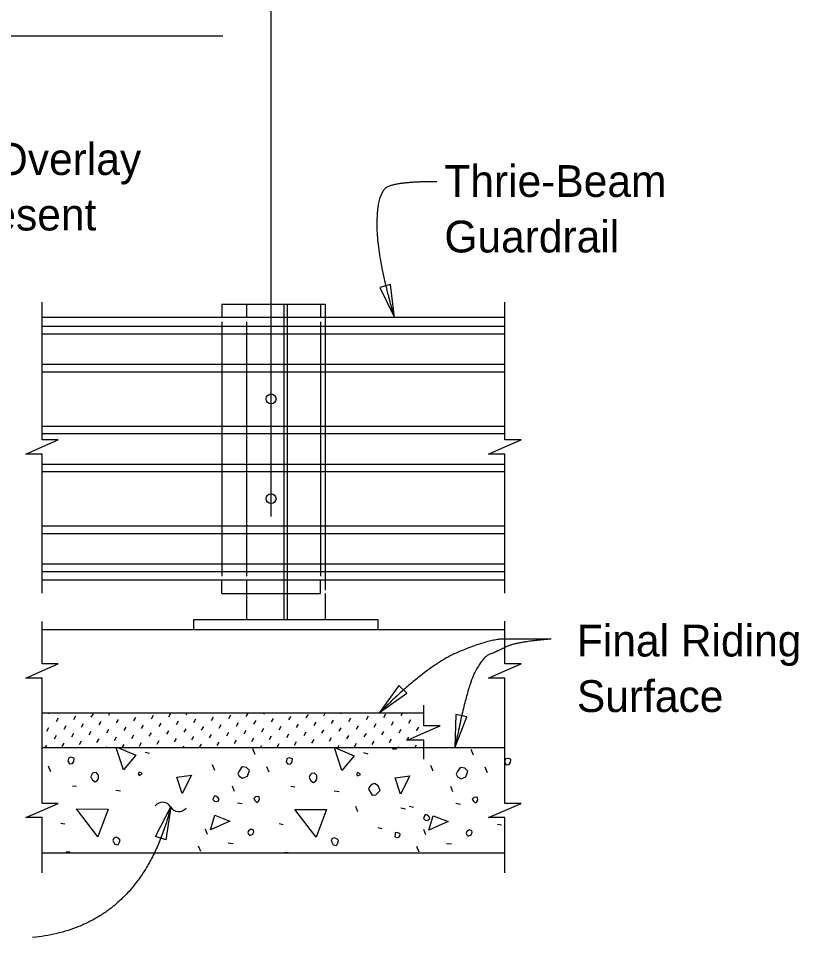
# Model space of a CAD drawing. Extents: x 21516.9 to 21586.2, y 56154.4 to 56193.6.
# Drawn here: x 21533.29 to 21538.24, y 56170.02 to 56175.85 of the extents above; entities that cross this region are included whole.
import ezdxf

# ---------------------------------------------------------------- set-up
doc = ezdxf.new("R2010")
doc.units = 0
for name, color, linetype in [('AdhocPoint_dp', 7, 'Continuous'), ('Border', 7, 'Continuous'), ('Patterning', 7, 'Continuous'), ('PlotBorder_dp', 7, 'Continuous'), ('TextMisc', 7, 'Continuous')]:
    doc.layers.add(name, color=color, linetype=linetype)

msp = doc.modelspace()

# ---------------------------------------------------------------- linework, layer by layer
at = {"layer": 'AdhocPoint_dp'}
for p, q in [((21533.4431, 56171.9698), (21536.3787, 56171.9698)), ((21535.8644, 56171.4388), (21533.4431, 56171.4388)), ((21536.3787, 56171.2198), (21533.4431, 56171.2198)), ((21533.4431, 56170.5532), (21536.3787, 56170.5532))]:
    msp.add_line(p, q, dxfattribs=at)
at = {"layer": 'Border'}
for p, q in [((21534.979, 56172.0324), (21534.979, 56174.0324)), ((21534.9998, 56172.0324), (21534.9998, 56174.0324)), ((21535.2394, 56174.0324), (21535.2394, 56172.2194)), ((21534.7394, 56173.9205), (21534.7394, 56172.3086))]:
    msp.add_line(p, q, dxfattribs=at)
at = {"layer": 'Patterning'}
for p, q in [((21534.5832, 56174.0324), (21535.2082, 56174.0324)), ((21534.5832, 56174.0324), (21534.5832, 56173.9491)), ((21535.2082, 56174.0324), (21535.2082, 56173.9491)), ((21534.5832, 56173.9205), (21534.5832, 56172.3086)), ((21535.2082, 56173.9205), (21535.2082, 56172.3086)), ((21534.5832, 56172.1991), (21534.5832, 56172.2824)), ((21535.2082, 56172.1991), (21535.2082, 56172.2824)), ((21534.5832, 56172.1991), (21535.2082, 56172.1991)), ((21533.4856, 56171.436), (21533.4872, 56171.4388)), ((21533.8663, 56171.4261), (21533.8737, 56171.4388)), ((21534.3577, 56171.4291), (21534.3633, 56171.4388)), ((21534.7384, 56171.4192), (21534.7498, 56171.4388)), ((21534.8491, 56171.4321), (21534.8529, 56171.4388)), ((21535.2298, 56171.4222), (21535.2394, 56171.4388)), ((21535.3404, 56171.4352), (21535.3425, 56171.4388)), ((21535.7212, 56171.4252), (21535.729, 56171.4388)), ((21535.8318, 56171.4382), (21535.8321, 56171.4388)), ((21533.5344, 56171.3872), (21533.5474, 56171.4096)), ((21533.6451, 56171.4002), (21533.658, 56171.4226)), ((21533.7557, 56171.4131), (21533.7687, 56171.4355)), ((21533.8045, 56171.3643), (21533.8175, 56171.3867)), ((21533.9152, 56171.3773), (21533.9281, 56171.3996)), ((21534.0258, 56171.3902), (21534.0388, 56171.4126)), ((21534.1364, 56171.4032), (21534.1494, 56171.4256)), ((21534.2471, 56171.4161), (21534.26, 56171.4385)), ((21534.2959, 56171.3673), (21534.3089, 56171.3897)), ((21534.4065, 56171.3803), (21534.4195, 56171.4027)), ((21534.5172, 56171.3932), (21534.5301, 56171.4156)), ((21534.6278, 56171.4062), (21534.6408, 56171.4286)), ((21534.7873, 56171.3703), (21534.8002, 56171.3927)), ((21534.8979, 56171.3833), (21534.9109, 56171.4057)), ((21535.0085, 56171.3963), (21535.0215, 56171.4187)), ((21535.1192, 56171.4092), (21535.1321, 56171.4316)), ((21535.168, 56171.3604), (21535.181, 56171.3828)), ((21535.2786, 56171.3734), (21535.2916, 56171.3957)), ((21535.3893, 56171.3863), (21535.4022, 56171.4087)), ((21535.4999, 56171.3993), (21535.5129, 56171.4217)), ((21535.6105, 56171.4122), (21535.6235, 56171.4346)), ((21535.6594, 56171.3634), (21535.6723, 56171.3858)), ((21535.77, 56171.3764), (21535.783, 56171.3988)), ((21533.4726, 56171.3254), (21533.4856, 56171.3478)), ((21533.5833, 56171.3384), (21533.5962, 56171.3608)), ((21533.6939, 56171.3513), (21533.7069, 56171.3737)), ((21533.7427, 56171.3025), (21533.7557, 56171.3249)), ((21533.8534, 56171.3155), (21533.8663, 56171.3378)), ((21533.964, 56171.3284), (21533.977, 56171.3508)), ((21534.0746, 56171.3414), (21534.0876, 56171.3638)), ((21534.1853, 56171.3543), (21534.1982, 56171.3767)), ((21534.2341, 56171.3055), (21534.2471, 56171.3279)), ((21534.3447, 56171.3185), (21534.3577, 56171.3409)), ((21534.4554, 56171.3314), (21534.4683, 56171.3538)), ((21534.566, 56171.3444), (21534.579, 56171.3668)), ((21534.6766, 56171.3574), (21534.6896, 56171.3798)), ((21534.7255, 56171.3085), (21534.7384, 56171.3309)), ((21534.8361, 56171.3215), (21534.8491, 56171.3439)), ((21534.9467, 56171.3345), (21534.9597, 56171.3569)), ((21535.0574, 56171.3474), (21535.0703, 56171.3698)), ((21535.2168, 56171.3116), (21535.2298, 56171.3339)), ((21535.3275, 56171.3245), (21535.3404, 56171.3469)), ((21535.4381, 56171.3375), (21535.4511, 56171.3599)), ((21535.5487, 56171.3504), (21535.5617, 56171.3728)), ((21535.5976, 56171.3016), (21535.6105, 56171.324)), ((21535.7082, 56171.3146), (21535.7212, 56171.337)), ((21535.8188, 56171.3275), (21535.8318, 56171.3499)), ((21533.5215, 56171.2766), (21533.5344, 56171.299)), ((21533.6321, 56171.2895), (21533.6451, 56171.3119)), ((21533.7916, 56171.2537), (21533.8045, 56171.2761)), ((21533.9022, 56171.2666), (21533.9152, 56171.289)), ((21534.0128, 56171.2796), (21534.0258, 56171.302)), ((21534.1235, 56171.2926), (21534.1364, 56171.3149)), ((21534.1723, 56171.2437), (21534.1853, 56171.2661)), ((21534.2829, 56171.2567), (21534.2959, 56171.2791)), ((21534.3936, 56171.2696), (21534.4065, 56171.292)), ((21534.5042, 56171.2826), (21534.5172, 56171.305)), ((21534.6148, 56171.2956), (21534.6278, 56171.318)), ((21534.6637, 56171.2467), (21534.6766, 56171.2691)), ((21534.7743, 56171.2597), (21534.7873, 56171.2821)), ((21534.8849, 56171.2727), (21534.8979, 56171.2951)), ((21534.9956, 56171.2856), (21535.0085, 56171.308)), ((21535.1062, 56171.2986), (21535.1192, 56171.321)), ((21535.155, 56171.2498), (21535.168, 56171.2721)), ((21535.2657, 56171.2627), (21535.2786, 56171.2851)), ((21535.3763, 56171.2757), (21535.3893, 56171.2981)), ((21535.4869, 56171.2886), (21535.4999, 56171.311)), ((21535.6464, 56171.2528), (21535.6594, 56171.2752)), ((21535.757, 56171.2657), (21535.77, 56171.2881)), ((21533.4626, 56171.2198), (21533.4726, 56171.2372)), ((21533.5703, 56171.2277), (21533.5833, 56171.2501)), ((21533.6809, 56171.2407), (21533.6939, 56171.2631)), ((21533.8491, 56171.2199), (21533.8534, 56171.2272)), ((21533.9522, 56171.2199), (21533.964, 56171.2402)), ((21534.0617, 56171.2308), (21534.0746, 56171.2531)), ((21534.3388, 56171.2199), (21534.3447, 56171.2302)), ((21534.4424, 56171.2208), (21534.4554, 56171.2432)), ((21534.553, 56171.2338), (21534.566, 56171.2562)), ((21534.7253, 56171.22), (21534.7255, 56171.2203)), ((21534.7949, 56171.1768), (21534.7808, 56171.2121)), ((21534.8284, 56171.22), (21534.8361, 56171.2333)), ((21534.9338, 56171.2238), (21534.9467, 56171.2462)), ((21535.0444, 56171.2368), (21535.0574, 56171.2592)), ((21535.2149, 56171.22), (21535.2168, 56171.2233)), ((21535.3181, 56171.2201), (21535.3275, 56171.2363)), ((21535.4251, 56171.2268), (21535.4381, 56171.2492)), ((21535.5358, 56171.2398), (21535.5487, 56171.2622)), ((21535.7046, 56171.2201), (21535.7082, 56171.2263)), ((21535.8077, 56171.2201), (21535.8188, 56171.2393)), ((21536.1796, 56171.1732), (21536.1655, 56171.2086)), ((21534.0967, 56171.1927), (21534.125, 56171.1856)), ((21535.4813, 56171.1891), (21535.5096, 56171.1821)), ((21533.498, 56171.0678), (21533.4839, 56171.1031)), ((21534.5386, 56171.076), (21534.5245, 56171.1114)), ((21534.8827, 56171.0642), (21534.8686, 56171.0996)), ((21535.9233, 56171.0725), (21535.9091, 56171.1078)), ((21536.2674, 56171.0607), (21536.2532, 56171.0961)), ((21533.6359, 56170.9794), (21533.6607, 56170.9759)), ((21534.6641, 56170.9434), (21534.6517, 56170.977)), ((21535.0206, 56170.9759), (21535.0453, 56170.9723)), ((21536.0488, 56170.9399), (21536.0364, 56170.9735)), ((21533.9117, 56170.9511), (21533.9417, 56170.9458)), ((21535.2964, 56170.9476), (21535.3264, 56170.9423)), ((21534.6829, 56170.8716), (21534.713, 56170.8663)), ((21536.0676, 56170.868), (21536.0977, 56170.8627)), ((21535.4448, 56170.8132), (21535.4325, 56170.8468)), ((21535.7189, 56170.8397), (21535.7471, 56170.8327)), ((21535.7713, 56170.8497), (21535.7995, 56170.8427)), ((21533.5617, 56170.7425), (21533.5882, 56170.7372)), ((21534.4926, 56170.6707), (21534.4803, 56170.7042)), ((21534.9463, 56170.739), (21534.9729, 56170.7337)), ((21535.5721, 56170.7142), (21535.5986, 56170.7089)), ((21535.8773, 56170.6671), (21535.865, 56170.7007)), ((21536.331, 56170.7354), (21536.3575, 56170.7301)), ((21534.4502, 56170.5611), (21534.4361, 56170.5964)), ((21534.6228, 56170.617), (21534.6547, 56170.6135)), ((21535.8349, 56170.5575), (21535.8208, 56170.5929)), ((21536.0075, 56170.6135), (21536.0393, 56170.6099))]:
    msp.add_line(p, q, dxfattribs=at)
for points in [[(21533.9594, 56171.0802), (21533.914, 56171.2198)], [(21533.9279, 56171.2198), (21534.0372, 56171.1721), (21533.9594, 56171.0802)], [(21535.3441, 56171.0766), (21535.2975, 56171.2198)], [(21535.3044, 56171.2198), (21535.4219, 56171.1685), (21535.3441, 56171.0766)], [(21535.6662, 56171.2198), (21535.6687, 56171.2139), (21535.6652, 56171.2174)], [(21535.6687, 56171.2139), (21535.6899, 56171.2139), (21535.6959, 56171.2198)], [(21533.6076, 56171.135), (21533.6165, 56171.119), (21533.6359, 56171.1208), (21533.6447, 56171.1332), (21533.6465, 56171.1526), (21533.6341, 56171.1579), (21533.6253, 56171.1597), (21533.6147, 56171.1562), (21533.6112, 56171.1526), (21533.6076, 56171.135)], [(21534.9923, 56171.1314), (21535.0011, 56171.1155), (21535.0206, 56171.1173), (21535.0294, 56171.1297), (21535.0312, 56171.1491), (21535.0188, 56171.1544), (21535.01, 56171.1562), (21534.9994, 56171.1526), (21534.9958, 56171.1491), (21534.9923, 56171.1314)], [(21536.377, 56171.1279), (21536.3858, 56171.112), (21536.4053, 56171.1137), (21536.4141, 56171.1261), (21536.4159, 56171.1456), (21536.4035, 56171.1509), (21536.3947, 56171.1526), (21536.384, 56171.1491), (21536.3805, 56171.1456), (21536.377, 56171.1279)], [(21534.6924, 56171.0389), (21534.7154, 56171.0265), (21534.7454, 56171.0389), (21534.7578, 56171.076), (21534.7401, 56171.0937), (21534.7172, 56171.099), (21534.7065, 56171.0919), (21534.6942, 56171.0725), (21534.6853, 56171.0566), (21534.6924, 56171.0389)], [(21536.0771, 56171.0353), (21536.1001, 56171.023), (21536.1301, 56171.0353), (21536.1425, 56171.0725), (21536.1248, 56171.0901), (21536.1018, 56171.0954), (21536.0912, 56171.0884), (21536.0789, 56171.0689), (21536.07, 56171.053), (21536.0771, 56171.0353)], [(21533.7526, 56171.036), (21533.7632, 56171.0147), (21533.7809, 56171.0041), (21533.795, 56171.0147), (21533.8021, 56171.0254), (21533.8021, 56171.0466), (21533.7862, 56171.0625), (21533.7667, 56171.0607), (21533.7579, 56171.0519), (21533.7526, 56171.036)], [(21534.0584, 56171.0448), (21534.0778, 56171.0536), (21534.0708, 56171.0607), (21534.0584, 56171.066), (21534.0531, 56171.0536), (21534.0584, 56171.0448)], [(21534.3318, 56170.9293), (21534.2982, 56171.0336), (21534.3919, 56171.0459), (21534.3318, 56170.9293)], [(21535.1373, 56171.0324), (21535.1479, 56171.0112), (21535.1655, 56171.0006), (21535.1797, 56171.0112), (21535.1868, 56171.0218), (21535.1868, 56171.043), (21535.1708, 56171.0589), (21535.1514, 56171.0572), (21535.1426, 56171.0483), (21535.1373, 56171.0324)], [(21535.4431, 56171.0413), (21535.4625, 56171.0501), (21535.4555, 56171.0572), (21535.4431, 56171.0625), (21535.4378, 56171.0501), (21535.4431, 56171.0413)], [(21535.7165, 56170.9257), (21535.6829, 56171.03), (21535.7766, 56171.0424), (21535.7165, 56170.9257)], [(21535.5138, 56170.9564), (21535.5368, 56170.9193), (21535.5598, 56170.9211), (21535.5686, 56170.9299), (21535.588, 56170.9493), (21535.5757, 56170.9794), (21535.5509, 56170.9935), (21535.5332, 56170.9865), (21535.5191, 56170.9723), (21535.5138, 56170.9564)], [(21534.5375, 56170.8803), (21534.5499, 56170.8785), (21534.5623, 56170.8838), (21534.5658, 56170.8944), (21534.5605, 56170.9033), (21534.5499, 56170.9103), (21534.5375, 56170.9156), (21534.5304, 56170.9015), (21534.5269, 56170.8909), (21534.5375, 56170.8803)], [(21534.7943, 56170.8839), (21534.8049, 56170.8733), (21534.8155, 56170.8804), (21534.8226, 56170.891), (21534.8191, 56170.9087), (21534.8102, 56170.9105), (21534.7978, 56170.9087), (21534.7872, 56170.8981), (21534.7943, 56170.8839)], [(21536.179, 56170.8804), (21536.1896, 56170.8698), (21536.2002, 56170.8769), (21536.2073, 56170.8875), (21536.2037, 56170.9051), (21536.1949, 56170.9069), (21536.1825, 56170.9051), (21536.1719, 56170.8945), (21536.179, 56170.8804)], [(21533.7968, 56170.6559), (21533.6624, 56170.8327), (21533.8622, 56170.8309), (21533.7968, 56170.6559)], [(21535.1815, 56170.6524), (21535.0471, 56170.8291), (21535.2469, 56170.8274), (21535.1815, 56170.6524)], [(21534.5115, 56170.7001), (21534.5398, 56170.792), (21534.6334, 56170.7549), (21534.5115, 56170.7001)], [(21535.8738, 56170.7613), (21535.8862, 56170.7596), (21535.8985, 56170.7649), (21535.9021, 56170.7755), (21535.8968, 56170.7843), (21535.8862, 56170.7914), (21535.8738, 56170.7967), (21535.8667, 56170.7825), (21535.8632, 56170.7719), (21535.8738, 56170.7613)], [(21535.8961, 56170.6966), (21535.9244, 56170.7885), (21536.0181, 56170.7514), (21535.8961, 56170.6966)], [(21534.759, 56170.6647), (21534.766, 56170.6647), (21534.7802, 56170.6718), (21534.7855, 56170.6877), (21534.7837, 56170.6966), (21534.7696, 56170.7036), (21534.7519, 56170.693), (21534.7483, 56170.6824), (21534.7519, 56170.6718), (21534.759, 56170.6647)], [(21535.68, 56170.6559), (21535.6994, 56170.6506), (21535.7118, 56170.6594), (21535.7135, 56170.6718), (21535.71, 56170.6753), (21535.6959, 56170.6824), (21535.6835, 56170.6806), (21535.6817, 56170.6683), (21535.68, 56170.6559)], [(21536.1436, 56170.6612), (21536.1507, 56170.6612), (21536.1648, 56170.6683), (21536.1701, 56170.6842), (21536.1684, 56170.693), (21536.1542, 56170.7001), (21536.1366, 56170.6895), (21536.133, 56170.6789), (21536.1366, 56170.6683), (21536.1436, 56170.6612)], [(21533.8958, 56170.6241), (21533.9046, 56170.6082), (21533.9258, 56170.6046), (21533.9347, 56170.6205), (21533.9382, 56170.6347), (21533.9294, 56170.6435), (21533.9134, 56170.6524), (21533.8975, 56170.6471), (21533.8922, 56170.6311), (21533.8958, 56170.6241)], [(21535.2804, 56170.6205), (21535.2893, 56170.6046), (21535.3105, 56170.6011), (21535.3193, 56170.617), (21535.3229, 56170.6311), (21535.314, 56170.64), (21535.2981, 56170.6488), (21535.2822, 56170.6435), (21535.2769, 56170.6276), (21535.2804, 56170.6205)], [(21533.621, 56170.5532), (21533.62, 56170.5569), (21533.597, 56170.5587), (21533.5952, 56170.5532)], [(21535.0047, 56170.5532), (21535.0047, 56170.5534), (21534.9817, 56170.5551), (21534.981, 56170.5532)]]:
    msp.add_lwpolyline(points, dxfattribs=at)
at = {"layer": 'PlotBorder_dp'}
for p, q in [((21534.8957, 56172.6864), (21534.8957, 56187.0198)), ((21534.5904, 56175.7323), (21529.056, 56175.7323))]:
    msp.add_line(p, q, dxfattribs=at)
for points in [[(21535.6775, 56173.9482), (21535.6524, 56174.1579), (21535.5847, 56174.138)], [(21535.5841, 56171.4429), (21535.7563, 56171.5652), (21535.7064, 56171.6151)], [(21536.0614, 56171.2193), (21536.1361, 56171.4169), (21536.0669, 56171.4305)], [(21534.2593, 56170.8446), (21534.2288, 56170.6356), (21534.1617, 56170.6573)]]:
    msp.add_lwpolyline(points, close=True, dxfattribs=at)
for points in [[(21533.4431, 56172.1993), (21533.4431, 56173.0825), (21533.3398, 56173.0825), (21533.4431, 56173.1275), (21533.5464, 56173.1725), (21533.4431, 56173.1725), (21533.4431, 56174.0455)], [(21536.3787, 56172.1993), (21536.3787, 56173.0825), (21536.2753, 56173.0825), (21536.3787, 56173.1275), (21536.482, 56173.1725), (21536.3787, 56173.1725), (21536.3787, 56174.0455)], [(21536.3787, 56171.1919), (21536.3787, 56171.6619), (21536.2753, 56171.6619), (21536.3787, 56171.7069), (21536.482, 56171.7519), (21536.3787, 56171.7519), (21536.3787, 56172.0228)], [(21533.4431, 56171.1919), (21533.4431, 56171.6619), (21533.3398, 56171.6619), (21533.4431, 56171.7069), (21533.5464, 56171.7519), (21533.4431, 56171.7519), (21533.4431, 56172.0199)], [(21535.8645, 56171.1479), (21535.8645, 56171.2688), (21535.7611, 56171.2688), (21535.8645, 56171.3138), (21535.9678, 56171.3588), (21535.8645, 56171.3588), (21535.8645, 56171.4893)], [(21533.4431, 56170.4268), (21533.4431, 56170.7774), (21533.3398, 56170.7774), (21533.4431, 56170.8224), (21533.5464, 56170.8674), (21533.4431, 56170.8674), (21533.4431, 56171.1919)], [(21536.3787, 56170.4268), (21536.3787, 56170.7774), (21536.2753, 56170.7774), (21536.3787, 56170.8224), (21536.482, 56170.8674), (21536.3787, 56170.8674), (21536.3787, 56171.1919)]]:
    msp.add_lwpolyline(points, dxfattribs=at)
for centre, start, end in [((21534.2069, 56170.8149), 30.00813, 141.73535), ((21534.3102, 56170.8746), 210.00813, 321.73535)]:
    msp.add_arc(centre, 0.0596, start, end, dxfattribs=at)
for points in [[(21535.9478, 56174.8098), (21535.7075, 56174.8098), (21535.5662, 56174.7462), (21535.5662, 56174.3255), (21535.6774, 56173.9482)], [(21536.6724, 56171.9095), (21536.4816, 56171.9095), (21536.2767, 56171.9095), (21535.8809, 56171.7398), (21535.5841, 56171.4429)], [(21536.6724, 56171.9095), (21536.4466, 56171.8911), (21536.3229, 56171.8274), (21536.2399, 56171.7974), (21536.1356, 56171.5976), (21536.0614, 56171.2193)], [(21534.2593, 56170.8446), (21534.0676, 56170.0853), (21533.383, 56170.0159)]]:
    msp.add_open_spline(points, degree=2, dxfattribs=at)
at = {"layer": 'TextMisc'}
for p, q in [((21534.7394, 56174.0324), (21535.2394, 56174.0324)), ((21534.7394, 56174.0324), (21534.7394, 56173.9491)), ((21536.3787, 56173.949), (21533.4431, 56173.949)), ((21533.4431, 56173.8935), (21536.3787, 56173.8935)), ((21533.4431, 56173.8452), (21536.3787, 56173.8452)), ((21533.4431, 56173.6524), (21536.3787, 56173.6524)), ((21533.4431, 56173.6042), (21536.3787, 56173.6042)), ((21533.4431, 56173.2602), (21536.3787, 56173.2602)), ((21533.4431, 56173.212), (21536.3787, 56173.212)), ((21533.4431, 56173.0192), (21536.3787, 56173.0192)), ((21533.4431, 56172.9711), (21536.3787, 56172.9711)), ((21533.4431, 56172.6271), (21536.3787, 56172.6271)), ((21533.4431, 56172.5789), (21536.3787, 56172.5789)), ((21533.4431, 56172.3861), (21536.3787, 56172.3861)), ((21533.4431, 56172.3378), (21536.3787, 56172.3378)), ((21536.3787, 56172.2823), (21533.4431, 56172.2823)), ((21534.7394, 56172.2824), (21534.7394, 56172.0324)), ((21535.2394, 56172.1991), (21535.2394, 56172.0324)), ((21534.4061, 56172.0324), (21535.5728, 56172.0324)), ((21534.4061, 56171.9699), (21534.4061, 56172.0324)), ((21534.7394, 56172.0324), (21535.2394, 56172.0324)), ((21535.5728, 56172.0324), (21535.5728, 56171.9699)), ((21534.4061, 56171.9699), (21535.5728, 56171.9699))]:
    msp.add_line(p, q, dxfattribs=at)
for centre in [(21534.8957, 56173.4323), (21534.8957, 56172.7992)]:
    msp.add_circle(centre, 0.0312, dxfattribs=at)

# ---------------------------------------------------------------- texts
at = {"layer": 'PlotBorder_dp'}
for s, p in [('Asphalt Overlay', (21532.1691, 56174.8526)), ('Thrie-Beam ', (21535.9946, 56174.7132)), ('when present', (21532.1691, 56174.5006)), ('Guardrail', (21535.9946, 56174.3612)), ('Final Riding ', (21536.8351, 56171.7987)), ('Surface', (21536.8351, 56171.4467))]:
    msp.add_text(s, height=0.2016, dxfattribs=at).set_placement(p)

doc.saveas('drawing.dxf')
